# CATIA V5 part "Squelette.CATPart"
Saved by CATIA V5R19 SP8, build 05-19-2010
Part number: Squelette
Publications: "Point.1", "Point.2", "Point.3", "Point.4", "Point.5", "Point.6", "Point.7"
Bounding box of the stored display mesh (mm): x 0 to 0, y -597.964 to 127.968, z -496.431 to 272.585
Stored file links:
  F:\Travail\2e année\IAO\Projet\Squelette.CATPart
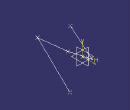
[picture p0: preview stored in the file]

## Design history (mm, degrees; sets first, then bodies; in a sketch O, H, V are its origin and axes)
Set1
  Point1: (0, 0, 0), relative to Sketch1.P5
  Point2: (0, 0, 0), relative to Sketch1.P1
  Point3: (0, 0, 0), relative to Sketch1.P2
  Point4: (0, 0, 0), relative to vertex [element of Sketch1 | element of Sketch1]
  Point5: (0, 0, 0)
  Point6: (0, 0, 0), relative to vertex [element of Sketch1 | element of Sketch1]
  Point7: (0, 0, 0), relative to Sketch1.P6
Body1 (main body)
  Sketch1 on yz-plane, origin (0, 0, 0), H (0, 1, 0), V (0, 0, 1)
    point P1 (68.2736, 19.4112)
    point P2 (0, 0)
    point P5 (-161.8532, 272.585)
    point P6 (-167.4113, -496.4309)
    line L1 (-196.4765, -38.7588) -> (127.9682, 32.5271)
    line L2 (-161.8532, 272.585) -> (127.9682, 32.5271)
    line L3 (-597.964, -82.8961) -> (-167.4113, -496.4309)
    line L4 (-597.964, -82.8961) -> (-196.4765, -38.7588)
    coincidence: P2 O, L1 P1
